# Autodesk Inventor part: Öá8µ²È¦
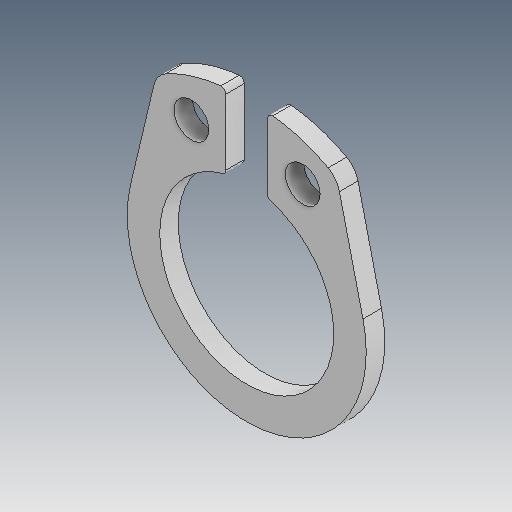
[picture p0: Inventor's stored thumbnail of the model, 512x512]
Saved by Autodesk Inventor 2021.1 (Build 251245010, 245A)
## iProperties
Created: 2019-05
Part Number: Öá8µ²È¦
Material: Ogólny
Document SubType Name: Modeling
Designer: user
Density: 1 g/cm^3
Appearance: Domyślna
Author: user
Revision Number: ÈÎºÎ
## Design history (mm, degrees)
feature "ÊäÈë1"
node "Bryła1"
